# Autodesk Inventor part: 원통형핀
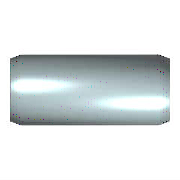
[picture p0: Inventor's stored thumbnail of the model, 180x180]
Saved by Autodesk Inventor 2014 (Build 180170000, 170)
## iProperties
IsCustomPart: 1
Created: 2012-02
Part Number: 원통형핀
Material: 강철, 연강
Description: 평행 핀
Document SubType Name: Modeling
Standard: KS B 1320
Designer: mduedu
Standards Organization: KS
Language: ko-KR
Size Designation: B 2 x  14
Categories: <MemberInstance><Categories><Category DisplayName="조임쇠" InternalName="e4da775c-781d-43d5-af7c-5136215cf5a6" Mnemonic="FSTN"><Category DisplayName="핀" InternalNa
Density: 1 g/cm^3
Appearance: 파란색 - 벽 페인트 - 광택
Author: mduedu
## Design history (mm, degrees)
sketch "스케치"
  geometry: C1 r 1 at (0, 0); 1 further point
  constraints: 1 centre point, 1 coincident
  dimensions: "d1" = 2 diameter of C1 (= NND)
extrude "본체" new body sketch "스케치" distance "d2" = 14 (= NLG); taper "d3" = 0 deg
chamfer "스케치2" distance "d8" = 0.35 (= PHH); stored, may be unused: angle "d9" = 15 deg (= FAWI), second distance "d12" = 0.35 (= PHH)
node "작업 평면1"
node "작업 평면2"
body "Solid1"
chamfer "모따기1" distance "d4" = 0.35 (= PHH); stored, may be unused: angle "d5" = 15 deg (= FAWI), second distance "d11" = 0.35 (= PHH)
other parameters: "NND" = 2 [user parameter; used in 1 equation term], "NLG" = 14 [user parameter; used in 1 equation term], "PHH" = 0.35 [user parameter; used in 4 equation terms], "FAWI" = 15 deg [user parameter; used in 2 equation terms], "d13" = 0, "d15" = 0, "d16" = 0, "KAH" = 0.25 [user parameter], "d17" = 7
